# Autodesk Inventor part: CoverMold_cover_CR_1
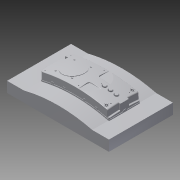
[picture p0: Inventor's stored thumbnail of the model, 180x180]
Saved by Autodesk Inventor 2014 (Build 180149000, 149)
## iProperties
Created: 2009-12
Part Number: CoverMold_cover_CR_1
Document SubType Name: Modeling
Designer: gaom
Density: 1 g/cm^3
Material: Generic
Appearance: Default
Author: gaom
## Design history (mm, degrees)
node "CoverMold_cover_CR_Base"
feature "Solid1::CoverMold_cover_CR_Base"
tag "TaggingFeature1"
body "Solid1"
